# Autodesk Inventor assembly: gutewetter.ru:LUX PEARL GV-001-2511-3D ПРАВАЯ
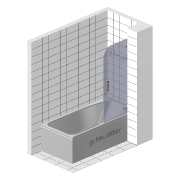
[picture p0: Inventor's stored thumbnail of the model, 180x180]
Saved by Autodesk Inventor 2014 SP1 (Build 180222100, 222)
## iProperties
Document SubType Name: Assembly
Designer: Чечуров
Mass: 20945.8 g
Surface Area: 367476 cm^2
Volume: 978698 cm^3
Density: 0.0214017 g/cm^3
Description: LUX PEARL GV-001-2511 ПРАВАЯ
RuleStatus: InUse
Author: Чечуров
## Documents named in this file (22)
- P:\!  Продукция GuteWetter\LUX динамические модели и набор документов\PEARL\LUX PEARL GV-001-2511\LUX PEARL GV-001-2511 правая модель\LUX PEARL GV-001-2511 ПРАВАЯ (модель).iam
- P:\!  Продукция GuteWetter\LUX динамические модели и набор документов\PEARL\LUX PEARL GV-001-2511\LUX PEARL GV-001-2511 правая модель\Вспомогательные файлы конструктора\Студия\Студия.ipt
- P:\!  Продукция GuteWetter\LUX динамические модели и набор документов\PEARL\LUX PEARL GV-001-2511\LUX PEARL GV-001-2511 правая модель\Вспомогательные файлы конструктора\Ручки\07.iam
- P:\!  Продукция GuteWetter\LUX динамические модели и набор документов\PEARL\LUX PEARL GV-001-2511\LUX PEARL GV-001-2511 правая модель\Вспомогательные файлы конструктора\Ручки\113.iam
- P:\!  Продукция GuteWetter\LUX динамические модели и набор документов\PEARL\LUX PEARL GV-001-2511\LUX PEARL GV-001-2511 правая модель\Вспомогательные файлы конструктора\Ручки\Ручка CH12-40.ipt
- P:\!  Продукция GuteWetter\LUX динамические модели и набор документов\PEARL\LUX PEARL GV-001-2511\LUX PEARL GV-001-2511 правая модель\Вспомогательные файлы конструктора\Ручки\Ручка CH02.ipt
- P:\!  Продукция GuteWetter\LUX динамические модели и набор документов\PEARL\LUX PEARL GV-001-2511\LUX PEARL GV-001-2511 правая модель\Вспомогательные файлы конструктора\Ручки\Ручка CH01.ipt
- P:\!  Продукция GuteWetter\LUX динамические модели и набор документов\PEARL\LUX PEARL GV-001-2511\LUX PEARL GV-001-2511 правая модель\Вспомогательные файлы конструктора\Ручки\Ручка CH04.ipt
- P:\!  Продукция GuteWetter\LUX динамические модели и набор документов\PEARL\LUX PEARL GV-001-2511\LUX PEARL GV-001-2511 правая модель\Вспомогательные файлы конструктора\Трап\Трап 100х100 (2).ipt
- P:\!  Продукция GuteWetter\LUX динамические модели и набор документов\PEARL\LUX PEARL GV-001-2511\LUX PEARL GV-001-2511 правая модель\Вспомогательные файлы конструктора\Упаковка\Упаковка.ipt
- P:\!  Продукция GuteWetter\LUX динамические модели и набор документов\PEARL\LUX PEARL GV-001-2511\LUX PEARL GV-001-2511 правая модель\Вспомогательные файлы конструктора\Студия\Пол.ipt
- P:\!  Продукция GuteWetter\LUX динамические модели и набор документов\PEARL\LUX PEARL GV-001-2511\LUX PEARL GV-001-2511 правая модель\Вспомогательные файлы конструктора\Ручки\112.iam
- P:\!  Продукция GuteWetter\LUX динамические модели и набор документов\PEARL\LUX PEARL GV-001-2511\LUX PEARL GV-001-2511 правая модель\Вспомогательные файлы конструктора\Петли\CH25-0 R.iam
- P:\!  Продукция GuteWetter\LUX динамические модели и набор документов\PEARL\LUX PEARL GV-001-2511\LUX PEARL GV-001-2511 правая модель\Вспомогательные файлы конструктора\Уплотнитель\UP600B6.01.ipt
- P:\!  Продукция GuteWetter\LUX динамические модели и набор документов\PEARL\LUX PEARL GV-001-2511\LUX PEARL GV-001-2511 правая модель\Вспомогательные файлы конструктора\Студия\Ванна\Ванна 170х80x50.iam
- P:\!  Продукция GuteWetter\LUX динамические модели и набор документов\PEARL\LUX PEARL GV-001-2511\LUX PEARL GV-001-2511 правая модель\Вспомогательные файлы конструктора\Уплотнитель\UP606-13.ipt
- P:\!  Продукция GuteWetter\LUX динамические модели и набор документов\PEARL\LUX PEARL GV-001-2511\LUX PEARL GV-001-2511 правая модель\Вспомогательные файлы конструктора\Студия\Стенка A.ipt
- P:\!  Продукция GuteWetter\LUX динамические модели и набор документов\PEARL\LUX PEARL GV-001-2511\LUX PEARL GV-001-2511 правая модель\Вспомогательные файлы конструктора\Крепеж\DUBEL 8x52.ipt
- P:\!  Продукция GuteWetter\LUX динамические модели и набор документов\PEARL\LUX PEARL GV-001-2511\LUX PEARL GV-001-2511 правая модель\Вспомогательные файлы конструктора\Крепеж\Саморез 6х55.ipt
- P:\!  Продукция GuteWetter\LUX динамические модели и набор документов\PEARL\LUX PEARL GV-001-2511\LUX PEARL GV-001-2511 правая модель\Вспомогательные файлы конструктора\Стекло\Стекло.03 (2511) PEARL.ipt
- P:\!  Продукция GuteWetter\LUX динамические модели и набор документов\PEARL\LUX PEARL GV-001-2511\LUX PEARL GV-001-2511 правая модель\Вспомогательные файлы конструктора\Петли\CH25-11 R.iam
- P:\!  Продукция GuteWetter\LUX динамические модели и набор документов\PEARL\LUX PEARL GV-001-2511\LUX PEARL GV-001-2511 правая модель\Вспомогательные файлы конструктора\Студия\LOGO GUTEWETTER.ipt
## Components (37 placed, 21 different names)
1. Студия:1 — Совмещение:514, Заподлицо:128, Заподлицо:129, Совмещение:668, Совмещение:669, Совмещение:758, Заподлицо:544
2. Трап 100х100 (2):1 — Заподлицо:130, Совмещение:515, Совмещение:516
3. Пол:1 — Совмещение:514, Заподлицо:128, Заподлицо:129, Заподлицо:130, Совмещение:515, Совмещение:516, Совмещение:667, Совмещение:757, Совмещение:763
4. Ванна 170х80x50:1 [sub-assembly] — Совмещение:667, Совмещение:668, Совмещение:669, Совмещение:748
5. Стекло.03 (2511) PEARL:1 — Совмещение:307, Совмещение:308, Совмещение:309, Совмещение:486, Совмещение:487, Заподлицо:119, Совмещение:488, Совмещение:489, Совмещение:490, Совмещение:491, Совмещение:492, Совмещение:493, Совмещение:494, Заподлицо:120, Совмещение:495, Совмещение:496, Заподлицо:497, Совмещение:498, Совмещение:526, Заподлицо:133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
6. CH25-0 R:1 [sub-assembly] — Совмещение:570, Совмещение:571, Совмещение:572, Совмещение:755, Совмещение:756
7. CH25-0 R:4 [sub-assembly] — Совмещение:567, Совмещение:568, Совмещение:569, Совмещение:753, Совмещение:754
8. UP600B6.01:1 — Совмещение:645, Совмещение:646, Заподлицо:526
9. 07:1 [sub-assembly] — Совмещение:307, Совмещение:308, Совмещение:309
10. 113:1 [sub-assembly] — Совмещение:486, Совмещение:487, Заподлицо:119
11. 112:1 [sub-assembly] — Совмещение:526, Заподлицо:133, Совмещение:527
12. Ручка CH12-40:1 — Совмещение:496, Заподлицо:497, Совмещение:498
13. Ручка CH01:1 — Совмещение:494, Заподлицо:120, Совмещение:495
14. Ручка CH02:1 — Совмещение:491, Совмещение:492, Совмещение:493
15. Ручка CH04:1 — Совмещение:488, Совмещение:489, Совмещение:490
16. Упаковка:1
17. UP606-13:1 — Совмещение:746, Заподлицо:543, Совмещение:747
18. Стенка A:1 — Совмещение:749, Совмещение:750, Совмещение:751, Совмещение:752, Совмещение:757, Совмещение:758, Совмещение:759, Совмещение:760, Совмещение:761, Совмещение:762, Угол:1
19. CH25-11 R:2 [sub-assembly] — Совмещение:730, Совмещение:731, Совмещение:732, Совмещение:733, Совмещение:734, Совмещение:735, Совмещение:736, Совмещение:737, Совмещение:749, Совмещение:752, Совмещение:753, Совмещение:754, Совмещение:759, Совмещение:762
20. DUBEL 8x52:9 — Совмещение:737
21. Саморез 6х55:9 — Совмещение:732
22. DUBEL 8x52:10 — Совмещение:734
23. Саморез 6х55:10 — Совмещение:733
24. DUBEL 8x52:11 — Совмещение:735
25. Саморез 6х55:11 — Совмещение:731
26. DUBEL 8x52:12 — Совмещение:736
27. Саморез 6х55:12 — Совмещение:730
28. CH25-11 R:1 [sub-assembly] — Совмещение:738, Совмещение:739, Совмещение:740, Совмещение:741, Совмещение:742, Совмещение:743, Совмещение:744, Совмещение:745, Совмещение:750, Совмещение:751, Совмещение:755, Совмещение:756, Совмещение:760, Совмещение:761
29. DUBEL 8x52:13 — Совмещение:745
30. Саморез 6х55:13 — Совмещение:740
31. DUBEL 8x52:14 — Совмещение:744
32. Саморез 6х55:14 — Совмещение:741
33. DUBEL 8x52:15 — Совмещение:742
34. Саморез 6х55:15 — Совмещение:739
35. DUBEL 8x52:16 — Совмещение:743
36. Саморез 6х55:16 — Совмещение:738
37. LOGO GUTEWETTER:1 — Совмещение:763, Заподлицо:544
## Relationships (76: Mate 65, Flush 10, Angle 1)
- Совмещение:307 [Mate]: Стекло.03 (2511) PEARL:1 ↔ 07:1
- Совмещение:308 [Mate]: Стекло.03 (2511) PEARL:1 ↔ 07:1
- Совмещение:309 [Mate]: Стекло.03 (2511) PEARL:1 ↔ 07:1
- Совмещение:486 [Mate]: Стекло.03 (2511) PEARL:1 ↔ 113:1
- Совмещение:487 [Mate]: Стекло.03 (2511) PEARL:1 ↔ 113:1
- Заподлицо:119 [Flush]: Стекло.03 (2511) PEARL:1 ↔ 113:1
- Совмещение:488 [Mate]: Стекло.03 (2511) PEARL:1 ↔ Ручка CH04:1
- Совмещение:489 [Mate]: Стекло.03 (2511) PEARL:1 ↔ Ручка CH04:1
- Совмещение:490 [Mate]: Стекло.03 (2511) PEARL:1 ↔ Ручка CH04:1
- Совмещение:491 [Mate]: Стекло.03 (2511) PEARL:1 ↔ Ручка CH02:1
- Совмещение:492 [Mate]: Стекло.03 (2511) PEARL:1 ↔ Ручка CH02:1
- Совмещение:493 [Mate]: Стекло.03 (2511) PEARL:1 ↔ Ручка CH02:1
- Совмещение:494 [Mate]: Стекло.03 (2511) PEARL:1 ↔ Ручка CH01:1
- Заподлицо:120 [Flush]: Стекло.03 (2511) PEARL:1 ↔ Ручка CH01:1
- Совмещение:495 [Mate]: Стекло.03 (2511) PEARL:1 ↔ Ручка CH01:1
- Совмещение:496 [Mate]: Стекло.03 (2511) PEARL:1 ↔ Ручка CH12-40:1
- Заподлицо:497 [Flush]: Стекло.03 (2511) PEARL:1 ↔ Ручка CH12-40:1
- Совмещение:498 [Mate]: Стекло.03 (2511) PEARL:1 ↔ Ручка CH12-40:1
- Совмещение:514 [Mate]: Студия:1 ↔ Пол:1
- Заподлицо:128 [Flush]: Студия:1 ↔ Пол:1
- Заподлицо:129 [Flush]: Студия:1 ↔ Пол:1
- Заподлицо:130 [Flush]: Трап 100х100 (2):1 ↔ Пол:1
- Совмещение:515 [Mate]: Трап 100х100 (2):1 ↔ Пол:1
- Совмещение:516 [Mate]: Трап 100х100 (2):1 ↔ Пол:1
- Совмещение:526 [Mate]: Стекло.03 (2511) PEARL:1 ↔ 112:1
- Заподлицо:133 [Flush]: Стекло.03 (2511) PEARL:1 ↔ 112:1
- Совмещение:527 [Mate]: Стекло.03 (2511) PEARL:1 ↔ 112:1
- Совмещение:567 [Mate]: Стекло.03 (2511) PEARL:1 ↔ CH25-0 R:4
- Совмещение:568 [Mate]: Стекло.03 (2511) PEARL:1 ↔ CH25-0 R:4
- Совмещение:569 [Mate]: Стекло.03 (2511) PEARL:1 ↔ CH25-0 R:4
- Совмещение:570 [Mate]: Стекло.03 (2511) PEARL:1 ↔ CH25-0 R:1
- Совмещение:571 [Mate]: Стекло.03 (2511) PEARL:1 ↔ CH25-0 R:1
- Совмещение:572 [Mate]: Стекло.03 (2511) PEARL:1 ↔ CH25-0 R:1
- Совмещение:645 [Mate]: Стекло.03 (2511) PEARL:1 ↔ UP600B6.01:1
- Совмещение:646 [Mate]: Стекло.03 (2511) PEARL:1 ↔ UP600B6.01:1
- Заподлицо:526 [Flush]: Стекло.03 (2511) PEARL:1 ↔ UP600B6.01:1
- Совмещение:667 [Mate]: Пол:1 ↔ Ванна 170х80x50:1
- Совмещение:668 [Mate]: Студия:1 ↔ Ванна 170х80x50:1
- Совмещение:669 [Mate]: Студия:1 ↔ Ванна 170х80x50:1
- Совмещение:730 [Mate]: CH25-11 R:2 ↔ Саморез 6х55:12
- Совмещение:731 [Mate]: CH25-11 R:2 ↔ Саморез 6х55:11
- Совмещение:732 [Mate]: CH25-11 R:2 ↔ Саморез 6х55:9
- Совмещение:733 [Mate]: CH25-11 R:2 ↔ Саморез 6х55:10
- Совмещение:734 [Mate]: CH25-11 R:2 ↔ DUBEL 8x52:10
- Совмещение:735 [Mate]: CH25-11 R:2 ↔ DUBEL 8x52:11
- Совмещение:736 [Mate]: CH25-11 R:2 ↔ DUBEL 8x52:12
- Совмещение:737 [Mate]: CH25-11 R:2 ↔ DUBEL 8x52:9
- Совмещение:738 [Mate]: CH25-11 R:1 ↔ Саморез 6х55:16
- Совмещение:739 [Mate]: CH25-11 R:1 ↔ Саморез 6х55:15
- Совмещение:740 [Mate]: CH25-11 R:1 ↔ Саморез 6х55:13
- Совмещение:741 [Mate]: CH25-11 R:1 ↔ Саморез 6х55:14
- Совмещение:742 [Mate]: CH25-11 R:1 ↔ DUBEL 8x52:15
- Совмещение:743 [Mate]: CH25-11 R:1 ↔ DUBEL 8x52:16
- Совмещение:744 [Mate]: CH25-11 R:1 ↔ DUBEL 8x52:14
- Совмещение:745 [Mate]: CH25-11 R:1 ↔ DUBEL 8x52:13
- Совмещение:746 [Mate]: Стекло.03 (2511) PEARL:1 ↔ UP606-13:1
- Заподлицо:543 [Flush]: Стекло.03 (2511) PEARL:1 ↔ UP606-13:1
- Совмещение:747 [Mate]: Стекло.03 (2511) PEARL:1 ↔ UP606-13:1
- Совмещение:748 [Mate]: Ванна 170х80x50:1 ↔ Стекло.03 (2511) PEARL:1
- Совмещение:749 [Mate]: Стенка A:1 ↔ CH25-11 R:2
- Совмещение:750 [Mate]: Стенка A:1 ↔ CH25-11 R:1
- Совмещение:751 [Mate]: Стенка A:1 ↔ CH25-11 R:1
- Совмещение:752 [Mate]: Стенка A:1 ↔ CH25-11 R:2
- Совмещение:753 [Mate]: CH25-0 R:4 ↔ CH25-11 R:2
- Совмещение:754 [Mate]: CH25-0 R:4 ↔ CH25-11 R:2
- Совмещение:755 [Mate]: CH25-0 R:1 ↔ CH25-11 R:1
- Совмещение:756 [Mate]: CH25-0 R:1 ↔ CH25-11 R:1
- Совмещение:757 [Mate]: Пол:1 ↔ Стенка A:1
- Совмещение:758 [Mate]: Студия:1 ↔ Стенка A:1
- Совмещение:759 [Mate]: Стенка A:1 ↔ CH25-11 R:2
- Совмещение:760 [Mate]: Стенка A:1 ↔ CH25-11 R:1
- Совмещение:761 [Mate]: Стенка A:1 ↔ CH25-11 R:1
- Совмещение:762 [Mate]: Стенка A:1 ↔ CH25-11 R:2
- Угол:1 [Angle]: Стекло.03 (2511) PEARL:1 ↔ Стенка A:1
- Совмещение:763 [Mate]: Пол:1 ↔ LOGO GUTEWETTER:1
- Заподлицо:544 [Flush]: Студия:1 ↔ LOGO GUTEWETTER:1
## Named parameters: d234_УГОЛ = 0, d242_УГОЛ = 0, d1041_d988_d719 = 0, d1042_d989_d720 = -7.5 mm, d1063_d1041_d988_d719 = 0, d1064_d1042_d989_d720 = -7.5 mm, d1065_d1063_d1041_d988_d719 = 0, d1066_d1064_d1042_d989_d720 = -7.5 mm, d1067_d1041_d988_d719 = 0, d1068_d1042_d989_d720 = -7.5 mm, d1202_d1041_d988_d719 = 0, d1203_d1042_d989_d720 = -7.5 mm, d1208_d1063_d1041_d988_d719 = 0, d1209_d1064_d1042_d989_d720 = -7.5 mm, d1210_d1065_d1063_d1041_d988_d719 = 0, d1211_d1066_d1064_d1042_d989_d720 = -7.5 mm, d1212_d1067_d1041_d988_d719 = 0, d1213_d1068_d1042_d989_d720 = -7.5 mm
